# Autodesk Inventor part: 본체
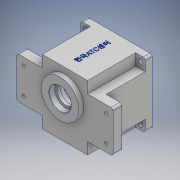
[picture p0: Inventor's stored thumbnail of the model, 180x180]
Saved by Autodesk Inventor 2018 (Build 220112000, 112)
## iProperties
Created: 2020-07
Part Number: 본체
Material: 알루미늄 6061
Document SubType Name: Modeling
Designer: Admin
Density: 2.7 g/cm^3
Appearance: 알루미늄 - 평지
Mass: 874.122 g
Surface Area: 794.874 cm^2
Volume: 323.749 cm^3
Author: Admin
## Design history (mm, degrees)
sketch "스케치5"
  geometry: L1 (47, 47)-(-47, 47); L2 (-47, 47)-(-47, -47); L3 (-47, -47)-(47, -47); L4 (47, -47)-(47, 47); L5 (47, 47)-(-47, -47); L6 (-47, 47)-(47, -47); 1 further point
  constraints: 12 end point, 2 midpoint, 2 parallel, 1 horizontal, 1 perpendicular
  dimensions: "d16" = 94 distance of L1.start L1.end; "d17" = 94 distance of L1.end L2.end
extrude "돌출5" new body sketch "스케치5" distance "d18" = 10; taper "d19" = 0 deg
sketch "스케치6"
  geometry: L1 (-33, 47)-(33, 47); L2 (33, 47)-(33, -47); L3 (33, -47)-(-33, -47); L4 (-33, -47)-(-33, 47); L5 (-33, 47)-(33, -47); L6 (33, 47)-(-33, -47); 1 further point
  constraints: 12 end point, 2 midpoint, 2 parallel, 1 horizontal, 1 perpendicular
  dimensions: "d20" = 66 distance of L1.start L1.end; "d21" = 94 distance of L1.end L2.end
extrude "돌출6" join sketch "스케치6" distance "d22" = 57; taper "d23" = 0 deg
sketch "스케치7"
  geometry: L1 (70, 30)-(70, -30); L2 (-70, -30)-(-70, 30); L3 (-70, 30)-(70, -30); L4 (70, 30)-(-70, -30); L5 (-33, 47)-(33, 47); L6 (33, -47)-(-33, -47); L7 (-33, 47)-(33, -47); L8 (33, 47)-(-33, -47); L9 (-70, 30)-(-33, 30); L10 (33, 30)-(70, 30); L11 (33, 47)-(33, 30); L12 (33, -30)-(33, -47); L13 (70, -30)-(33, -30); L14 (-33, -30)-(-70, -30); L15 (-33, -47)-(-33, -30); L16 (-33, 30)-(-33, 47); 1 further point
  constraints: 32 end point, 10 parallel, 4 midpoint, 4 perpendicular, 3 horizontal
  dimensions: "d24" = 140 distance of L2.end L1.start; "d25" = 60 distance of L1.start L1.end; "d26" = 66 distance of L5.start L5.end; "d27" = 94 distance of L5.end L6.start
extrude "돌출7" join sketch "스케치7" distance "d28" = 13; taper "d29" = 0 deg
sketch "스케치8"
  geometry: L1 (-103, 0)-(-66, 0) reference; L2 (-66, 0)-(-66, -13) reference; L3 (-103, -13)-(-66, -13) reference; L4 (-103, 0)-(-103, -13) reference; L5 (14, 67)-(-80, 67) reference; L6 (14, 67)-(14, 57) reference; L7 (0, 57)-(14, 57) reference; L8 (0, 57)-(0, -13) reference; L9 (-66, -13)-(0, -13) reference; L10 (-66, 57)-(-66, -13) reference; L11 (-80, 57)-(-66, 57) reference; L12 (-80, 67)-(-80, 57) reference; L13 (0, 0)-(37, 0) reference; L14 (37, 0)-(37, -13) reference; L15 (0, -13)-(37, -13) reference; L16 (0, 0)-(0, -13) reference; L17 (-80, 67)-(-80, 57) reference; L18 (-80, 57)-(-80, 0); L19 (-103, 0)-(-66, 0) reference; L20 (-80, 0)-(-66, 0); L21 (-66, 0)-(-66, 57); L22 (-80, 57)-(-66, 57) reference; L23 (-66, 57)-(-80, 57); L24 (14, 57)-(14, 0); L25 (0, 0)-(37, 0) reference; L26 (14, 0)-(0, 0); L27 (0, 57)-(0, -13) reference; L28 (0, 57)-(13.166, 57); L29 (0, 57)-(14, 57) reference; L30 (0, 57)-(0, 0); 1 further point
  constraints: 16 end point, 4 collinear, 4 point on line, 2 perpendicular
extrude "돌출8" join sketch "스케치8" distance "d30" = 60; taper "d31" = 0 deg
sketch "스케치9"
  geometry: L1 (-70, 30)-(-70, -30) reference; L2 (-70, -30)-(-33, -30) reference; L3 (-33, -30)-(-33, -47) reference; L4 (-33, -47)-(33, -47) reference; L5 (33, -47)-(33, -30) reference; L6 (33, -30)-(70, -30) reference; L7 (70, -30)-(70, 30) reference; L8 (70, 30)-(33, 30) reference; L9 (33, 30)-(33, 47) reference; L10 (33, 47)-(-33, 47) reference; L11 (-33, 47)-(-33, 30) reference; L12 (-33, 30)-(-70, 30) reference; L13 (-104.394, 11)-(123.857, 11); L14 (0, -65.8)-(0, 65.8) reference; C1 r 27.5 at (0, 11); 1 further point
  constraints: 2 end point, 2 point on line, 1 centre point, 1 horizontal
  dimensions: "d32" = 11 distance from line of L13 point (0, 0); "d33" = 55 diameter of C1
extrude "돌출9" join sketch "스케치9" distance "d34" = 7; taper "d35" = 0 deg
sketch "스케치10"
  geometry: C1 r 27.5 at (0, 0) reference; C2 r 16 at (0, 0); 1 further point
  constraints: 1 centre point, 1 coincident
  dimensions: "d36" = 32 diameter of C2
extrude "돌출10" cut sketch "스케치10" distance "d37" = 8.3; taper "d38" = 0 deg
sketch "스케치11"
  geometry: C1 r 16 at (0, 0) reference; C2 r 12.5 at (0, 0); 1 further point
  constraints: 1 centre point, 1 coincident
  dimensions: "d39" = 25 diameter of C2
extrude "돌출11" cut sketch "스케치11" distance "d40" = 4.7; taper "d41" = 0 deg
sketch "스케치12"
  geometry: C1 r 12.5 at (0, 0) reference; C2 r 17.5 at (0, 0); 1 further point
  constraints: 1 centre point, 1 coincident
  dimensions: "d42" = 35 diameter of C2
extrude "돌출12" cut sketch "스케치12" distance "d43" = 10; taper "d44" = 0 deg
sketch "스케치13"
  geometry: C1 r 43 at (0, 0); 1 further point
  constraints: 1 centre point, 1 coincident
  dimensions: "d45" = 86 diameter of C1
extrude "돌출13" cut sketch "스케치13" distance "d46" = 9; taper "d47" = 0 deg
sketch "스케치14"
  geometry: L1 (-98, 0)-(98, 0) reference; L2 (0, 65.8)-(0, -65.8) reference; L3 (35.778, -3.994)-(39.8, -3.994); L4 (35.778, 3.994)-(39.8, 3.994); L5 (-35.778, -3.994)-(-39.8, -3.994); L6 (-35.778, 3.994)-(-39.8, 3.994); A1 r 36 centre (0, 0) between (36, 0) and (-36, 0); A2 r 4 centre (36, 0) between (36.222, 3.994) and (36.222, -3.994); A3 r 4 centre (-36, 0) between (-36.222, -3.994) and (-36.222, 3.994); A4 r 40 centre (0, 0) between (39.8, 3.994) and (-39.8, 3.994); A5 r 40 centre (0, 0) between (-39.8, -3.994) and (39.8, -3.994); 1 further point
  constraints: 18 point on circle, 8 end point, 8 point on line, 5 centre point, 2 coincident, 1 horizontal, 1 parallel
  dimensions: "d49" = 72 diameter of A1; "d50" = 8 diameter of A3; "d51" = 8 diameter of A2; "d52" = 40 radius of A5; "d53" = 40 radius of A4
extrude "돌출14" cut sketch "스케치14" distance "d54" = 55; taper "d55" = 0 deg
sketch "스케치15"
  geometry: L1 (-78.7, -5)-(-78.7, 27) reference; L2 (-87, -5)-(-87, 27) reference; L3 (-87, 27)-(-78.7, 27) reference; L4 (-87, -5)-(-78.7, -5) reference; L5 (-86.2, 27)-(-87, 27.462); L6 (-87, 27.462)-(-87, 27); L7 (-87, 38.5)-(-87, -16.5) reference; L8 (-87, 27)-(-86.2, 27); L9 (-107.231, 11)-(-35.59, 11); 1 further point
  constraints: 8 end point, 1 collinear, 1 horizontal, 1 perpendicular, 1 point on line
  dimensions: "d56" = 30 deg angle of L3 L5; "d57" = 0.8 distance from line of L7 L5.start; "d58" = 16 distance between parallel lines of L9 L3
revolve "회전1" sketch "스케치15" stored, may be unused: angle "d59" = 90 deg
sketch "스케치16"
  geometry: L1 (83.382, 20)-(-123.857, 20); L2 (-165.305, 0)-(124.83, 0) reference; L3 (0, 65.8)-(0, -65.8) reference; C1 r 11 at (0, 20); 1 further point
  constraints: 2 end point, 2 point on line, 1 centre point, 1 horizontal
  dimensions: "d60" = 20 distance from line of point (0, 0) L1; "d61" = 22 diameter of C1
extrude "돌출15" cut sketch "스케치16" distance "d62" = 7; taper "d63" = 0 deg
sketch "스케치17"
  geometry: C1 r 11 at (0, 0) reference; C2 r 9.5 at (0, 0); 1 further point
  constraints: 1 centre point, 1 coincident
  dimensions: "d64" = 19 diameter of C2
extrude "돌출16" cut sketch "스케치17" distance "d65" = 3; taper "d66" = 0 deg
sketch "스케치18"
  geometry: C1 r 17.5 at (0, -11) reference; C2 r 11 at (0, 20) reference; C3 r 40 at (0, 0); A1 r 21 centre (0, -11) between (-8.978, 7.984) and (8.978, 7.984); A2 r 15 centre (0, 20) between (8.978, 7.984) and (-8.978, 7.984); 1 further point
  constraints: 4 point on circle, 3 centre point, 3 coincident
  dimensions: "d67" = 42 diameter of A1; "d68" = 30 diameter of A2; "d69" = 80 diameter of C3
extrude "돌출17" cut sketch "스케치18" distance "d70" = 7; taper "d71" = 0 deg
sketch "스케치19"
  geometry: A1 r 4 centre (36, 0) between (36.222, 3.994) and (36.222, -3.994) reference; A2 r 4 centre (-36, 0) between (-36.222, -3.994) and (-36.222, 3.994) reference; 3 further points
  constraints: 2 coincident
hole "구멍1" sketch "스케치19" at (36, 0), (-36, 0) diameter "d72" = 3.242; stored, may be unused: countersink angle "d76" = 90 deg, drill point angle "d78" = 118 deg; dims "d73" = 7, "d74" = 4, "d75" = 2, "d77" = 9
sketch "스케치20"
  geometry: L1 (-70, 30)-(-70, -30) reference; L2 (-70, -30)-(-33, -30) reference; L3 (-33, -30)-(-33, -47) reference; L4 (-33, -47)-(33, -47) reference; L5 (33, -47)-(33, -30) reference; L6 (33, -30)-(70, -30) reference; L7 (70, -30)-(70, 30) reference; L8 (70, 30)-(33, 30) reference; L9 (33, 30)-(33, 47) reference; L10 (33, 47)-(-33, 47) reference; L11 (-33, 47)-(-33, 30) reference; L12 (-33, 30)-(-70, 30) reference; L13 (-60, 19)-(60, 19); L14 (60, 19)-(60, -19); L15 (60, -19)-(-60, -19); L16 (-60, -19)-(-60, 19); L17 (-60, 19)-(60, -19); L18 (60, 19)-(-60, -19); C1 r 27.5 at (0, 11) reference; C2 r 2.25 at (-60, 19); C3 r 2.25 at (-60, -19); C4 r 2.25 at (60, -19); C5 r 2.25 at (60, 19); 1 further point
  constraints: 12 end point, 4 centre point, 4 coincident, 2 midpoint, 2 parallel, 1 horizontal, 1 perpendicular
  dimensions: "d79" = 38 distance of L13.end L14.end; "d80" = 120 distance of L13.start L13.end; "d81" = 4.5 diameter of C2; "d82" = 4.5 diameter of C3; "d83" = 4.5 diameter of C4; "d84" = 4.5 diameter of C5
extrude "돌출18" cut sketch "스케치20" distance "d85" = 8; taper "d86" = 0 deg
sketch "스케치21"
  geometry: L1 (-130, 11)-(-130, -49) reference; L2 (-130, -49)-(-93, -49) reference; L3 (-93, -49)-(-93, -66) reference; L4 (-93, -66)-(-27, -66) reference; L5 (-27, -66)-(-27, -49) reference; L6 (-27, -49)-(10, -49) reference; L7 (10, -49)-(10, 11) reference; L8 (10, 11)-(-27, 11) reference; L9 (-27, 11)-(-27, 28) reference; L10 (-27, 28)-(-93, 28) reference; L11 (-93, 28)-(-93, 11) reference; L12 (-93, 11)-(-130, 11) reference; C1 r 2.25 at (0, -38) reference; C2 r 2.25 at (-120, 0) reference; C3 r 2.25 at (-120, -38) reference; C4 r 2.25 at (0, 0) reference; C5 r 27.5 at (-60, -8) reference; C6 r 5 at (-120, 0); C7 r 5 at (-120, -38); C8 r 5 at (0, -38); C9 r 5 at (0, 0); 1 further point
  constraints: 4 centre point, 4 coincident
  dimensions: "d87" = 10 diameter of C9; "d88" = 10 diameter of C8; "d89" = 10 diameter of C7; "d90" = 10 diameter of C6
extrude "돌출19" cut sketch "스케치21" distance "d91" = 5; taper "d92" = 0 deg
sketch "스케치22"
  geometry: L1 (-40, 40)-(40, 40); L2 (40, 40)-(40, -40); L3 (40, -40)-(-40, -40); L4 (-40, -40)-(-40, 40); L5 (-40, 40)-(40, -40); L6 (40, 40)-(-40, -40); C1 r 3.5 at (-40, 40); C2 r 3.5 at (40, 40); C3 r 3.5 at (40, -40); C4 r 3.5 at (-40, -40); 1 further point
  constraints: 12 end point, 4 centre point, 4 coincident, 2 midpoint, 2 parallel, 1 horizontal, 1 perpendicular
  dimensions: "d93" = 80 distance of L1.start L1.end; "d94" = 80 distance of L1.end L2.end; "d95" = 7 diameter of C1; "d96" = 7 diameter of C2; "d97" = 7 diameter of C3; "d98" = 7 diameter of C4
extrude "돌출20" cut sketch "스케치22" distance "d99" = 10; taper "d100" = 0 deg
sketch "스케치23" dims "d16" = 94, "d17" = 94
  geometry: L1 (47, -104.4)-(47, 17.4) reference; L2 (0, 0)-(94, 0) reference; 2 further points
  constraints: 1 point on line, 1 other
  dimensions: "d101" = 40 distance from line of L2 point (47, -40)
feature "엠보싱1" sketch "스케치23" dims "d16" = 94, "d17" = 94, "d24" = 140, "d25" = 60, "d26" = 66, "d27" = 94, "d102" = 0.5, "d103" = 0
chamfer "모따기1" distance "d104" = 1; stored, may be unused: second distance "d105" = 2, angle "d106" = 45 deg
chamfer "모따기2" distance "d107" = 1; stored, may be unused: second distance "d108" = 2, angle "d109" = 45 deg
chamfer "모따기3" distance "d110" = 1; stored, may be unused: second distance "d111" = 2, angle "d112" = 45 deg
fillet "모깎기1" dims "d113" = 3
fillet "모깎기2" dims "d114" = 3
fillet "모깎기3" dims "d115" = 3
fillet "모깎기4" dims "d116" = 3
fillet "모깎기5" dims "d117" = 3
node "솔리드2"
node "투영된 루프4"
node "투영된 루프5"
node "투영된 루프6"
node "투영된 루프7"
node "투영된 루프8"
node "투영된 루프9"
node "투영된 루프10"
node "투영된 루프11"
node "투영된 루프12"
